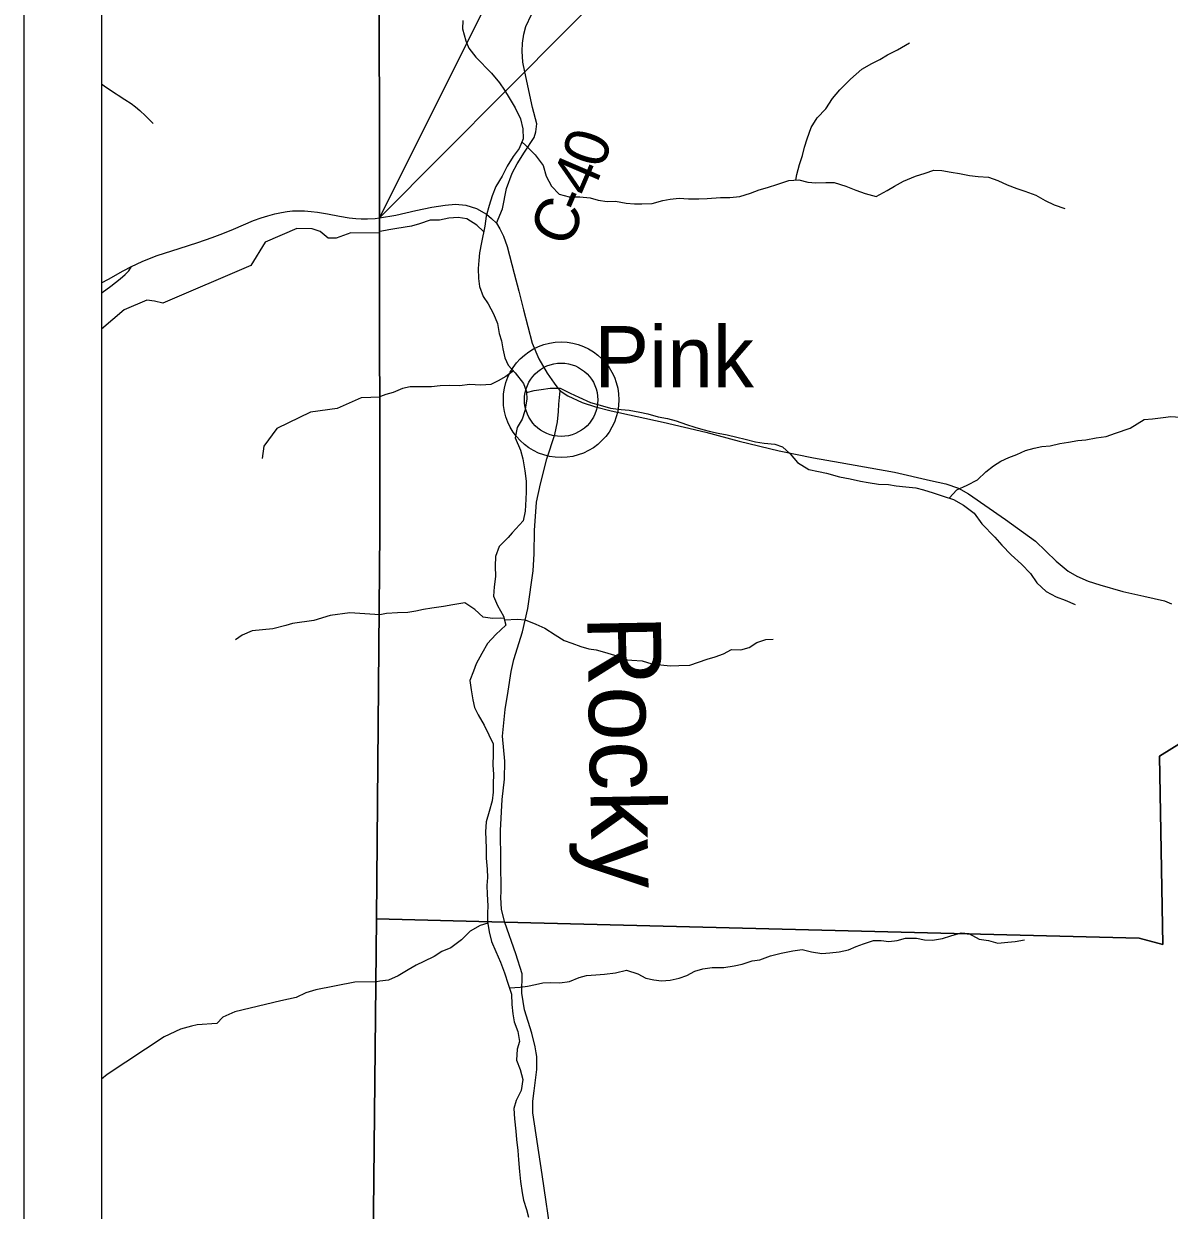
# Model space of a CAD drawing. Extents: x 0 to 34, y 0 to 22.
# Drawn here: x 2 to 3.475, y 16.905 to 18.432 of the extents above; entities that cross this region are included whole.
import ezdxf

# ---------------------------------------------------------------- set-up
doc = ezdxf.new("R2010")
doc.units = 0
for name, color, linetype in [('Default', 7, 'Continuous'), ('GM_X_County_Road', 7, 'Continuous'), ('GM_X_County_Road_Text', 7, 'Continuous'), ('GM_X_Minor_River', 7, 'Continuous'), ('GM_X_Minor_River_Text', 7, 'Continuous'), ('GM_X_State_Route', 7, 'Continuous'), ('GM_X_Township_Road', 7, 'Continuous'), ('GM_X_Unincorporated', 7, 'Continuous'), ('GM_X_Unincorporated_Location', 7, 'Continuous'), ('GM_X_Unincorporated_Text', 7, 'Continuous'), ('SH_Cut_Line', 7, 'Continuous'), ('SH_Data', 7, 'Continuous'), ('SH_Text', 7, 'Continuous')]:
    doc.layers.add(name, color=color, linetype=linetype)

msp = doc.modelspace()

# ---------------------------------------------------------------- linework, layer by layer
at = {"layer": 'Default'}
for points in [[(2.4313, 15.0183), (2.4545, 17.2795), (2.4586, 17.7785), (2.4581, 18.1772), (2.4581, 18.1825), (2.4573, 18.9074), (2.4757, 20.2566), (2.4809, 20.6393), (2.4845, 20.9), (2.1, 20.9), (2.1, 14.9328)], [(6.416, 20.9), (2.4845, 20.9), (2.4809, 20.6393), (2.4757, 20.2566), (2.4573, 18.9074), (2.4581, 18.1825), (2.4581, 18.1772), (2.4586, 17.7785), (2.4545, 17.2795), (2.6193, 17.2753), (3.4366, 17.255), (3.467, 17.2465), (3.4629, 17.4891), (3.5442, 17.5398)], [(3.5442, 17.5398), (3.4629, 17.4891), (3.467, 17.2465), (3.4366, 17.255), (2.6193, 17.2753), (2.4545, 17.2795), (2.4313, 15.0183)]]:
    msp.add_lwpolyline(points, dxfattribs=at)
at = {"layer": 'GM_X_County_Road'}
msp.add_line((2.6089, 18.1751), (2.6168, 18.1934), dxfattribs=at)
for points in [[(2.6168, 18.1934), (2.6219, 18.2199), (2.629, 18.2394), (2.6354, 18.2514), (2.6451, 18.2664), (2.6573, 18.2852), (2.6596, 18.2926), (2.6607, 18.303), (2.6552, 18.3241), (2.6453, 18.3699), (2.643, 18.3824), (2.6418, 18.3966), (2.6423, 18.4068), (2.644, 18.4185), (2.6466, 18.4282), (2.654, 18.4437)], [(2.6601, 17.1072), (2.6588, 17.1148), (2.6544, 17.1326), (2.645, 17.1627), (2.6417, 17.1841), (2.6419, 17.2088), (2.6339, 17.2347), (2.6195, 17.2748), (2.6154, 17.2915), (2.6145, 17.3074), (2.6148, 17.3143), (2.6142, 17.3933), (2.6162, 17.4332), (2.6192, 17.4596), (2.6198, 17.4828), (2.6165, 17.5147), (2.6201, 17.5491), (2.6239, 17.5729), (2.6277, 17.598), (2.6313, 17.6134), (2.6423, 17.6491), (2.6491, 17.6791), (2.6559, 17.7275), (2.6573, 17.7494), (2.6579, 17.7797), (2.6603, 17.8158), (2.6654, 17.8395), (2.6738, 17.8718), (2.6842, 17.9031), (2.6873, 17.9195), (2.6889, 17.9325), (2.6893, 17.9422), (2.691, 17.9592)], [(2.6801, 16.8655), (2.6677, 16.9508), (2.6558, 17.0298), (2.6556, 17.045), (2.6574, 17.0584), (2.6608, 17.0858), (2.6609, 17.1024), (2.6601, 17.1072)]]:
    msp.add_lwpolyline(points, dxfattribs=at)
at = {"layer": 'GM_X_Minor_River'}
for points in [[(2.5654, 18.4361), (2.5653, 18.4251), (2.5694, 18.4099), (2.5731, 18.4004), (2.5822, 18.3886), (2.6025, 18.368), (2.6127, 18.3557), (2.619, 18.3462), (2.625, 18.3363), (2.6329, 18.3234), (2.6396, 18.3093), (2.6426, 18.2964), (2.6433, 18.2838), (2.6379, 18.271), (2.6302, 18.2608), (2.6226, 18.2483), (2.6161, 18.2354), (2.608, 18.2222), (2.6034, 18.2101), (2.5995, 18.198), (2.5957, 18.1839), (2.5937, 18.1711), (2.5894, 18.1502)], [(2.9943, 18.2305), (2.9957, 18.2376), (2.9992, 18.2508), (3.0031, 18.2622), (3.0054, 18.2728), (3.0089, 18.2838), (3.0143, 18.2982), (3.0219, 18.3107), (3.033, 18.3224), (3.0418, 18.3356), (3.051, 18.3465), (3.0647, 18.3605), (3.0795, 18.3733), (3.0921, 18.3804), (3.1027, 18.3857), (3.1126, 18.3917), (3.1255, 18.398), (3.1407, 18.4071)], [(2.6415, 18.2796), (2.6466, 18.2751), (2.6587, 18.2632), (2.6688, 18.2491), (2.6729, 18.2354), (2.6796, 18.2229), (2.6898, 18.2126), (2.7023, 18.2091), (2.7163, 18.209), (2.7296, 18.2078), (2.7398, 18.2047), (2.7515, 18.2031), (2.7621, 18.2034), (2.7757, 18.201), (2.7867, 18.1998), (2.7962, 18.1998), (2.8095, 18.2004), (2.8231, 18.2041), (2.8326, 18.206), (2.844, 18.2074), (2.8561, 18.2066), (2.8694, 18.2065), (2.8803, 18.2068), (2.8974, 18.2082), (2.9095, 18.2081), (2.9224, 18.2096), (2.9361, 18.2137), (2.9471, 18.2178), (2.9577, 18.2211), (2.9714, 18.2252), (2.9854, 18.2301), (2.9983, 18.2307), (3.0097, 18.228), (3.0203, 18.2272), (3.0332, 18.2275), (3.0438, 18.2274), (3.0589, 18.2228), (3.0717, 18.2177), (3.0835, 18.2131), (3.0978, 18.2096), (3.1119, 18.2171), (3.1214, 18.2227), (3.1332, 18.2291), (3.1484, 18.2355), (3.1609, 18.2396), (3.1723, 18.2433), (3.1825, 18.2429), (3.1943, 18.2409), (3.2052, 18.2389), (3.2181, 18.2366), (3.2291, 18.2353), (3.2423, 18.2341), (3.2544, 18.2299), (3.2665, 18.2245), (3.279, 18.2199), (3.2892, 18.2164), (3.3036, 18.211), (3.3153, 18.2044), (3.327, 18.1987), (3.341, 18.194)], [(2.5923, 18.1643), (2.5835, 18.1723), (2.5706, 18.1807), (2.5593, 18.1823), (2.5475, 18.1816), (2.5354, 18.179), (2.5233, 18.1791), (2.5096, 18.1742), (2.4993, 18.1713), (2.4804, 18.1684), (2.4701, 18.1665), (2.459, 18.1645)], [(2.459, 18.162), (2.4214, 18.1628), (2.4023, 18.1557), (2.3921, 18.1559), (2.3817, 18.1645), (2.3716, 18.1678), (2.3516, 18.1683), (2.3111, 18.1507), (2.2925, 18.1204), (2.179, 18.072), (2.1685, 18.0745), (2.1587, 18.0759), (2.1292, 18.0637), (2.1, 18.0387)], [(2.5894, 18.1502), (2.587, 18.1369), (2.5862, 18.1271), (2.5854, 18.1168), (2.5857, 18.1039), (2.5868, 18.0937), (2.5916, 18.0807), (2.598, 18.0712), (2.6051, 18.0583), (2.61, 18.0461), (2.6125, 18.0332), (2.6155, 18.0237), (2.617, 18.0134), (2.6195, 18.0016), (2.624, 17.9921), (2.6331, 17.9826), (2.6436, 17.9688), (2.6477, 17.9582), (2.648, 17.9487), (2.6452, 17.9335), (2.6418, 17.9229), (2.6353, 17.912), (2.6329, 17.8987), (2.6396, 17.8831), (2.643, 17.8717), (2.6455, 17.8565), (2.6473, 17.8432), (2.6469, 17.8292), (2.6468, 17.8197), (2.6456, 17.8045), (2.6432, 17.792), (2.6289, 17.7766)], [(2.6308, 17.9849), (2.6209, 17.9777), (2.611, 17.9721), (2.6015, 17.9676), (2.5886, 17.9665), (2.5742, 17.9674), (2.5617, 17.9656), (2.5485, 17.966), (2.5363, 17.9657), (2.5253, 17.9643), (2.4977, 17.9645), (2.4878, 17.9622), (2.4757, 17.957), (2.4662, 17.9544), (2.4593, 17.952)], [(2.6477, 17.957), (2.6572, 17.9597), (2.6666, 17.9611), (2.678, 17.9629), (2.6909, 17.9629), (2.7037, 17.9563), (2.7151, 17.9513), (2.7298, 17.9444), (2.7423, 17.9409), (2.7559, 17.937), (2.7695, 17.9354), (2.7798, 17.9346), (2.7934, 17.9319), (2.8036, 17.9295), (2.8172, 17.926), (2.8293, 17.9237), (2.8403, 17.9205), (2.8535, 17.9159), (2.8645, 17.9124), (2.8747, 17.9093), (2.8845, 17.907), (2.8944, 17.905), (2.9061, 17.9027), (2.9182, 17.8996), (2.9292, 17.8972), (2.9424, 17.8937), (2.9534, 17.8921), (2.9674, 17.8905), (2.9772, 17.8874), (2.987, 17.8783), (2.9964, 17.8672), (3.0112, 17.858), (3.0236, 17.8556), (3.0339, 17.8533), (3.0505, 17.8486), (3.0645, 17.8459), (3.0777, 17.8432), (3.0876, 17.8412), (3.1008, 17.8392), (3.1137, 17.8388), (3.1235, 17.8368), (3.136, 17.8356), (3.1489, 17.8344), (3.1588, 17.832), (3.1712, 17.8278), (3.1841, 17.8235), (3.1973, 17.8196), (3.2102, 17.812), (3.2241, 17.802), (3.2339, 17.7883), (3.2508, 17.771)], [(2.4593, 17.9512), (2.4347, 17.9501), (2.4038, 17.9364), (2.3692, 17.9319), (2.326, 17.911), (2.3091, 17.8879), (2.3072, 17.872)], [(3.1919, 17.8212), (3.2019, 17.8317), (3.2152, 17.8377), (3.2282, 17.8449), (3.2392, 17.855), (3.2491, 17.8626), (3.2586, 17.8686), (3.2685, 17.8734), (3.2791, 17.8772), (3.2902, 17.8824), (3.3012, 17.8854), (3.311, 17.8876), (3.322, 17.8887), (3.3345, 17.8916), (3.3455, 17.8931), (3.3577, 17.8953), (3.3679, 17.8963), (3.3812, 17.8989), (3.3941, 17.9004), (3.4059, 17.9048), (3.4248, 17.9111), (3.443, 17.9225)], [(3.443, 17.9225), (3.4539, 17.9232), (3.4675, 17.925), (3.4774, 17.9261), (3.4892, 17.9253), (3.5028, 17.9195), (3.513, 17.9133), (3.5266, 17.9072), (3.5402, 17.9018), (3.5527, 17.8967)], [(2.6289, 17.7766), (2.6239, 17.7705), (2.6124, 17.7588), (2.6078, 17.7459), (2.6073, 17.7334), (2.6076, 17.7205), (2.606, 17.7072), (2.6051, 17.695), (2.61, 17.6828), (2.6178, 17.6691), (2.6208, 17.6577), (2.6082, 17.6456), (2.5975, 17.6339), (2.5898, 17.6211), (2.5829, 17.6078), (2.5794, 17.5984), (2.5747, 17.5866), (2.5762, 17.5745), (2.5783, 17.5615), (2.5805, 17.5516), (2.5854, 17.5421), (2.5929, 17.5291), (2.5989, 17.5166), (2.6048, 17.5048), (2.6044, 17.4915), (2.6043, 17.4774), (2.6049, 17.466), (2.6045, 17.4535), (2.6044, 17.4429), (2.6032, 17.4315), (2.5996, 17.4178), (2.5957, 17.4046), (2.5949, 17.3916), (2.5952, 17.3818), (2.5955, 17.37), (2.5954, 17.3578), (2.5968, 17.3438), (2.5971, 17.3328), (2.5966, 17.3225), (2.5969, 17.3115), (2.5976, 17.2963), (2.5971, 17.2868), (2.5974, 17.2762), (2.5996, 17.2629), (2.6026, 17.2503), (2.6082, 17.2377), (2.6141, 17.224), (2.6193, 17.2103), (2.6238, 17.1958), (2.6282, 17.1829), (2.6285, 17.1696), (2.6299, 17.1574), (2.6318, 17.1472), (2.6362, 17.1346), (2.6384, 17.1217), (2.6357, 17.1118), (2.6348, 17.0978), (2.6393, 17.0856), (2.643, 17.0727), (2.6406, 17.0586), (2.6344, 17.0458), (2.6313, 17.0355), (2.632, 17.0222), (2.6337, 17.0066), (2.6348, 16.9956), (2.6362, 16.9816), (2.6373, 16.9694), (2.6383, 16.9546), (2.6397, 16.9417), (2.6419, 16.9272), (2.6437, 16.9177), (2.6474, 16.9055), (2.65, 16.8956)], [(3.2508, 17.771), (3.2598, 17.7608), (3.2715, 17.7482), (3.2851, 17.7363), (3.2964, 17.7241), (3.3046, 17.7123), (3.3167, 17.7012), (3.3295, 17.6943), (3.3413, 17.69), (3.3541, 17.6842)], [(2.6186, 17.6661), (2.6137, 17.6665), (2.6038, 17.6662), (2.5917, 17.6678), (2.5811, 17.6777), (2.5683, 17.6862), (2.5527, 17.684), (2.5405, 17.6818), (2.5257, 17.6796), (2.5147, 17.6778), (2.5052, 17.6756), (2.4949, 17.6741), (2.4813, 17.6735), (2.4672, 17.6728), (2.4586, 17.6711)], [(2.4586, 17.6711), (2.4202, 17.6734), (2.3945, 17.6701), (2.3736, 17.6638), (2.3463, 17.6597), (2.3376, 17.6571), (2.3209, 17.6531), (2.294, 17.6502), (2.2815, 17.6449), (2.2727, 17.6389)], [(2.619, 17.6647), (2.636, 17.6652), (2.6459, 17.6644), (2.6595, 17.659), (2.6712, 17.6536), (2.6845, 17.6451), (2.6962, 17.6378), (2.706, 17.6343), (2.7177, 17.6301), (2.728, 17.6273), (2.7374, 17.6258), (2.748, 17.623), (2.7609, 17.6191), (2.7722, 17.6134), (2.7832, 17.6125), (2.7965, 17.6117), (2.809, 17.6078), (2.8204, 17.6066), (2.8325, 17.6054), (2.8439, 17.6057), (2.858, 17.6063), (2.88, 17.6138), (2.8903, 17.6167), (2.9013, 17.6208), (2.9116, 17.6265), (2.9234, 17.626), (2.9344, 17.629), (2.9443, 17.6354), (2.9557, 17.6391), (2.9652, 17.6398)], [(2.5978, 17.2741), (2.5879, 17.2709), (2.575, 17.2638), (2.5639, 17.2525), (2.5501, 17.2423), (2.5383, 17.2375), (2.5288, 17.2314), (2.5151, 17.2247), (2.5056, 17.2202), (2.4953, 17.2142), (2.4823, 17.2063), (2.4697, 17.2007), (2.4587, 17.1996), (2.4547, 17.1986)], [(2.6255, 17.1908), (2.6393, 17.1916), (2.6488, 17.193), (2.6591, 17.1952), (2.6686, 17.1974), (2.6781, 17.1978), (2.6906, 17.1973), (2.7027, 17.1991), (2.7153, 17.204), (2.7248, 17.2066), (2.7366, 17.2076), (2.748, 17.2083), (2.762, 17.2101), (2.7765, 17.2134), (2.7908, 17.2088), (2.801, 17.2034), (2.8113, 17.201), (2.8215, 17.1998), (2.8325, 17.2009), (2.8443, 17.2035), (2.8538, 17.2068), (2.8645, 17.2124), (2.8744, 17.2154), (2.8865, 17.2172), (2.9017, 17.2171), (2.915, 17.2193), (2.9253, 17.2215), (2.9382, 17.2256), (2.9481, 17.2271), (2.9618, 17.2319), (2.9755, 17.2356), (2.9907, 17.2385), (3.0024, 17.24), (3.0146, 17.2372), (3.0278, 17.2352), (3.0381, 17.2359), (3.0502, 17.237), (3.0624, 17.2399), (3.0719, 17.2441), (3.0814, 17.2474), (3.0944, 17.2519), (3.1042, 17.2518), (3.1141, 17.2506), (3.1247, 17.2517), (3.1357, 17.2546), (3.1498, 17.2549), (3.16, 17.2526), (3.1703, 17.2521), (3.1832, 17.2543), (3.1938, 17.2577), (3.2071, 17.2617), (3.217, 17.2609), (3.2306, 17.2536), (3.2423, 17.252), (3.2545, 17.2485), (3.2674, 17.2496), (3.2769, 17.2503), (3.289, 17.2528)], [(2.4547, 17.1986), (2.4264, 17.198), (2.3764, 17.1884), (2.3635, 17.1846), (2.351, 17.1786), (2.3312, 17.1742), (2.2721, 17.1601), (2.2565, 17.153), (2.2489, 17.1451), (2.2235, 17.1433), (2.2159, 17.1414), (2.2019, 17.1377), (2.181, 17.1276), (2.1076, 17.0794), (2.1, 17.0732)]]:
    msp.add_lwpolyline(points, dxfattribs=at)
at = {"layer": 'GM_X_State_Route'}
for points in [[(2.1, 18.0982), (2.1091, 18.1032), (2.1281, 18.1137), (2.139, 18.1192), (2.1527, 18.1256), (2.1642, 18.1304), (2.1717, 18.1333), (2.2001, 18.1426), (2.2243, 18.1503), (2.2425, 18.1565), (2.2565, 18.1618), (2.2703, 18.1674), (2.296, 18.1783), (2.306, 18.1819), (2.3143, 18.1845), (2.3233, 18.1869), (2.3319, 18.1887), (2.3393, 18.19), (2.3461, 18.1908), (2.3536, 18.1911), (2.3617, 18.191), (2.3704, 18.1903), (2.3784, 18.1892), (2.3913, 18.1869), (2.4065, 18.1839), (2.4193, 18.1819), (2.4279, 18.1809), (2.4347, 18.1805), (2.4427, 18.1806), (2.4526, 18.1813), (2.4583, 18.1819)], [(2.4583, 18.1819), (2.4794, 18.1854), (2.5049, 18.1912), (2.5258, 18.1956), (2.5429, 18.1984), (2.5562, 18.1995), (2.5694, 18.1982), (2.583, 18.194), (2.5959, 18.1865), (2.6023, 18.1811), (2.6089, 18.1751)], [(2.6089, 18.1751), (2.613, 18.168), (2.6181, 18.1585), (2.6226, 18.1451), (2.6318, 18.1103), (2.6377, 18.0875), (2.6436, 18.0635), (2.655, 18.0206), (2.6635, 18.0004), (2.674, 17.9821), (2.6832, 17.9692), (2.6878, 17.9629), (2.691, 17.9592)], [(2.691, 17.9592), (2.7009, 17.9529), (2.7191, 17.9443), (2.7364, 17.9387), (2.7564, 17.9335), (2.8235, 17.9189), (2.8784, 17.9059), (2.9215, 17.8947), (2.973, 17.8821), (3.017, 17.8729), (3.0515, 17.8671), (3.1214, 17.8546), (3.1678, 17.8438), (3.1876, 17.8395), (3.2038, 17.8342), (3.2166, 17.8267), (3.2642, 17.7936), (3.3032, 17.7658), (3.3296, 17.74), (3.345, 17.7273), (3.3564, 17.7206), (3.3708, 17.7143), (3.386, 17.7097), (3.4154, 17.7011), (3.4427, 17.6949), (3.469, 17.689), (3.478, 17.6851)]]:
    msp.add_lwpolyline(points, dxfattribs=at)
at = {"layer": 'GM_X_Township_Road'}
for points in [[(2.1, 18.3546), (2.1038, 18.352), (2.113, 18.3456), (2.1191, 18.3414), (2.1218, 18.3397), (2.1301, 18.3343), (2.1384, 18.3289), (2.144, 18.3249), (2.1496, 18.3201), (2.1568, 18.3133), (2.1669, 18.3034)], [(2.1, 18.0849), (2.1011, 18.0857), (2.112, 18.0938), (2.1241, 18.1035), (2.1307, 18.1092), (2.1353, 18.1138), (2.139, 18.1192)]]:
    msp.add_lwpolyline(points, dxfattribs=at)
at = {"layer": 'GM_X_Unincorporated'}
for radius in [0.0744, 0.0472]:
    msp.add_circle((2.6921, 17.9478), radius, dxfattribs=at)
at = {"layer": 'GM_X_Unincorporated_Location'}
msp.add_line((2.6921, 17.9478), (2.6921, 17.9478), dxfattribs=at)
at = {"layer": 'SH_Cut_Line'}
for points in [[(2.4845, 20.9), (2.1, 20.9), (2.1, 14.1), (2.4352, 14.1), (2.4372, 14.2719), (2.4313, 15.0183), (2.4545, 17.2795), (2.4586, 17.7785), (2.4581, 18.1772), (2.4581, 18.1825), (2.4573, 18.9074), (2.4757, 20.2566), (2.4809, 20.6393)], [(2.4352, 14.1), (8.9, 14.1), (8.9, 20.9), (2.4845, 20.9), (2.4809, 20.6393), (2.4757, 20.2566), (2.4573, 18.9074), (2.4581, 18.1825), (2.4581, 18.1772), (2.4586, 17.7785), (2.4545, 17.2795), (2.4313, 15.0183), (2.4372, 14.2719)]]:
    msp.add_lwpolyline(points, close=True, dxfattribs=at)
at = {"layer": 'SH_Data'}
for p, q in [((2, 21), (2, 14)), ((2.1, 20.9), (2.1, 14.1))]:
    msp.add_line(p, q, dxfattribs=at)
at = {"layer": 'SH_Text'}
msp.add_lwpolyline([(2.9469, 19.1594), (2.4583, 18.1819), (2.9469, 18.673)], close=True, dxfattribs=at)

# ---------------------------------------------------------------- texts
at = {"layer": 'GM_X_County_Road_Text'}
for s, rotation, p in [('0', 71.473, (2.7455, 18.2436)), ('4', 66.765, (2.7299, 18.2066)), ('C', 65.8287, (2.7011, 18.1417)), ('-', 66.6271, (2.7205, 18.1851))]:
    msp.add_text(s, height=0.0568, rotation=rotation, dxfattribs=at).set_placement(p)
at = {"layer": 'GM_X_Minor_River_Text'}
msp.add_text('Rocky', height=0.0947, rotation=271.0324, dxfattribs=at).set_placement((2.7257, 17.6699))
at = {"layer": 'GM_X_Unincorporated_Text'}
msp.add_text('Pink', height=0.07898, rotation=0, dxfattribs=at).set_placement((2.735, 17.9636))

doc.saveas('drawing.dxf')
